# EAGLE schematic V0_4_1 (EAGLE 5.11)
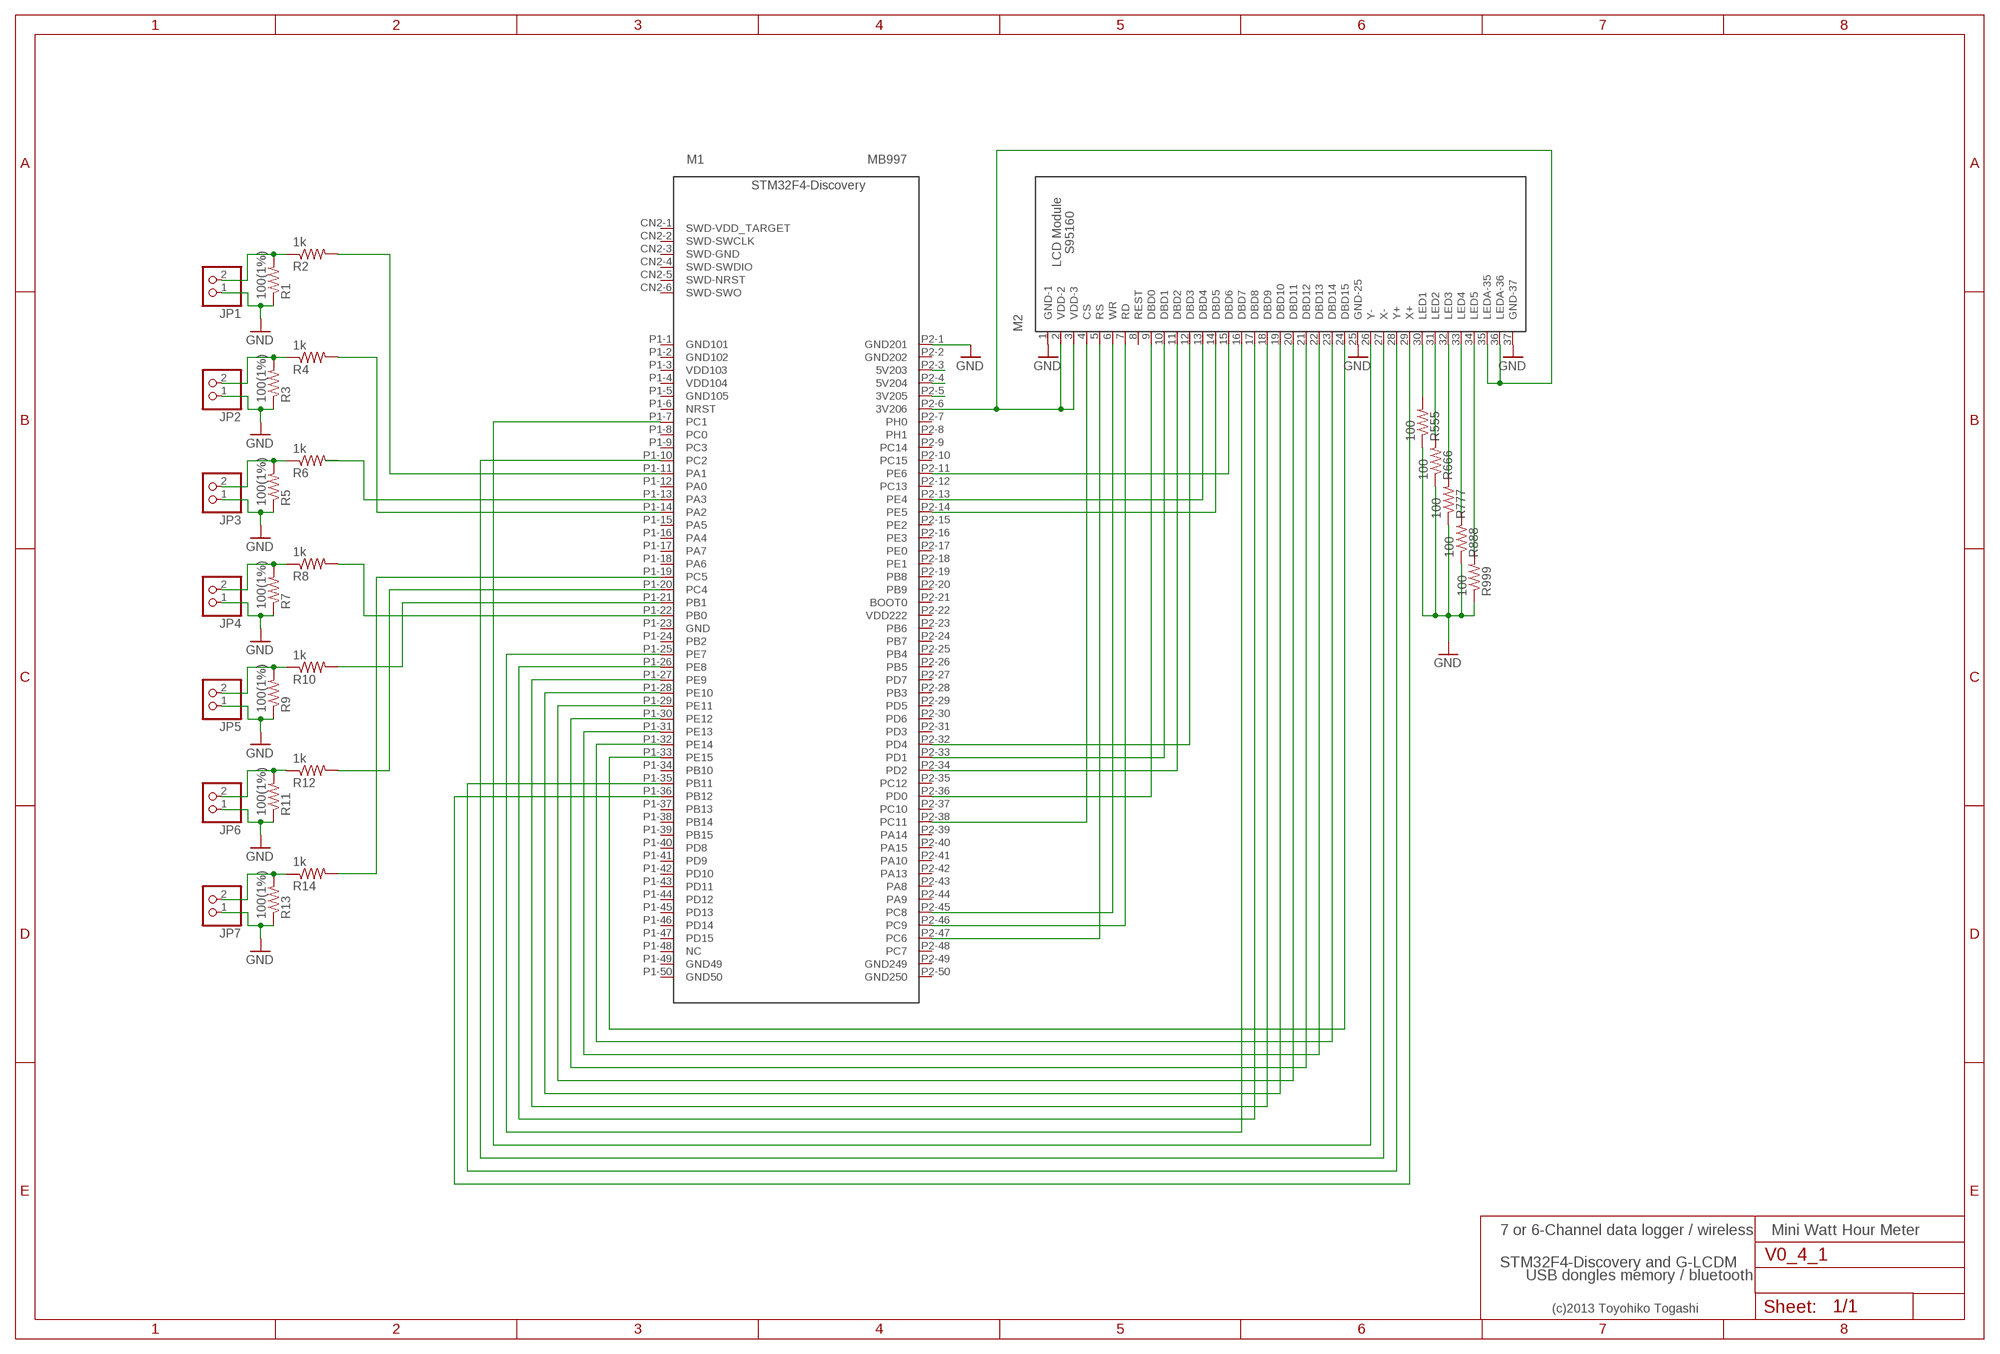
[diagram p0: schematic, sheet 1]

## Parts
JP1  PINHD-1X2  [1X02]
JP2  PINHD-1X2  [1X02]
JP3  PINHD-1X2  [1X02]
JP4  PINHD-1X2  [1X02]
JP5  PINHD-1X2  [1X02]
JP6  PINHD-1X2  [1X02]
JP7  PINHD-1X2  [1X02]
M1  MB997  [MB997]
M2  S95160  [S95160]
R1  100(1%)  R-US_0204/5  [0204/5]
R2  1k  R-US_0204/5  [0204/5]
R3  100(1%)  R-US_0204/5  [0204/5]
R4  1k  R-US_0204/5  [0204/5]
R5  100(1%)  R-US_0204/5  [0204/5]
R6  1k  R-US_0204/5  [0204/5]
R7  100(1%)  R-US_0204/5  [0204/5]
R8  1k  R-US_0204/5  [0204/5]
R9  100(1%)  R-US_0204/5  [0204/5]
R10  1k  R-US_0204/5  [0204/5]
R11  100(1%)  R-US_0204/5  [0204/5]
R12  1k  R-US_0204/5  [0204/5]
R13  100(1%)  R-US_0204/5  [0204/5]
R14  1k  R-US_0204/5  [0204/5]
R555  100  R-US_0204/5  [0204/5]
R666  100  R-US_0204/5  [0204/5]
R777  100  R-US_0204/5  [0204/5]
R888  100  R-US_0204/5  [0204/5]
R999  100  R-US_0204/5  [0204/5]

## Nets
GND: JP1.1 JP2.1 JP3.1 JP4.1 JP5.1 JP6.1 JP7.1 M1.P2-1(GND201) M2.1(GND-1) M2.25(GND-25) M2.37(GND-37) R1.1 R3.1 R5.1 R7.1 R9.1 R11.1 R13.1 R555.1 R666.1 R777.1 R888.1 R999.1
N$1: M1.P2-36(PD0) M2.9(DBD0)
N$2: M1.P2-33(PD1) M2.10(DBD1)
N$3: JP1.2 R1.2 R2.1
N$4: M1.P2-4(5V204)
N$5: M1.P2-3(5V203)
N$6: M1.P2-5(3V205)
N$7: M1.P1-11(PA1) R2.2
N$8: JP2.2 R3.2 R4.1
N$9: M1.P1-14(PA2) R4.2
N$10: JP3.2 R5.2 R6.1
N$11: M1.P2-34(PD2) M2.11(DBD2)
N$12: JP4.2 R7.2 R8.1
N$13: M1.P1-21(PB1) R10.2
N$14: M1.P2-6(3V206) M2.2(VDD-2) M2.3(VDD-3) M2.35(LEDA-35) M2.36(LEDA-36)
N$15: M1.P2-32(PD4) M2.12(DBD3)
N$16: M1.P1-20(PC4) R12.2
N$17: M1.P2-13(PE4) M2.13(DBD4)
N$18: M1.P2-14(PE5) M2.14(DBD5)
N$19: M1.P2-11(PE6) M2.15(DBD6)
N$20: M1.P1-19(PC5) R14.2
N$21: M1.P1-25(PE7) M2.16(DBD7)
N$22: M1.P1-26(PE8) M2.17(DBD8)
N$23: M1.P1-27(PE9) M2.18(DBD9)
N$24: M1.P1-28(PE10) M2.19(DBD10)
N$25: M1.P1-13(PA3)
N$26: M1.P1-22(PB0) R8.2
N$27: M1.P1-29(PE11) M2.20(DBD11)
N$28: M1.P1-30(PE12) M2.21(DBD12)
N$29: M1.P1-31(PE13) M2.22(DBD13)
N$30: M1.P1-32(PE14) M2.23(DBD14)
N$31: M1.P2-47(PC6) M2.5(RS)
N$32: M1.P1-33(PE15) M2.24(DBD15)
N$33: M1.P2-45(PC8) M2.6(WR)
N$34: M1.P2-46(PC9) M2.7(RD)
N$35: M1.P2-38(PC11) M2.4(CS)
N$36: M1.P1-7(PC1) M2.26(Y-)
N$37: M1.P1-10(PC2) M2.27(X-)
N$38: M1.P1-35(PB11) M2.28(Y+)
N$39: M1.P1-36(PB12) M2.29(X+)
N$40: JP5.2 R9.2 R10.1
N$41: JP6.2 R11.2 R12.1
N$42: M2.30(LED1) R555.2
N$43: M2.31(LED2) R666.2
N$44: M2.32(LED3) R777.2
N$45: M2.33(LED4) R888.2
N$46: M2.34(LED5) R999.2
N$47: JP7.2 R13.2 R14.1
Unconnected: M1.CN2-1(SWD-VDD_TARGET) M1.CN2-2(SWD-SWCLK) M1.CN2-3(SWD-GND) M1.CN2-4(SWD-SWDIO) M1.CN2-5(SWD-NRST) M1.CN2-6(SWD-SWO) M1.P1-1(GND101) M1.P1-2(GND102) M1.P1-3(VDD103) M1.P1-4(VDD104) M1.P1-5(GND105) M1.P1-6(NRST) M1.P1-8(PC0) M1.P1-9(PC3) M1.P1-12(PA0) M1.P1-15(PA5) M1.P1-16(PA4) M1.P1-17(PA7) M1.P1-18(PA6) M1.P1-23(GND) M1.P1-24(PB2) M1.P1-34(PB10) M1.P1-37(PB13) M1.P1-38(PB14) M1.P1-39(PB15) M1.P1-40(PD8) M1.P1-41(PD9) M1.P1-42(PD10) M1.P1-43(PD11) M1.P1-44(PD12) M1.P1-45(PD13) M1.P1-46(PD14) M1.P1-47(PD15) M1.P1-48(NC) M1.P1-49(GND49) M1.P1-50(GND50) M1.P2-2(GND202) M1.P2-7(PH0) M1.P2-8(PH1) M1.P2-9(PC14) M1.P2-10(PC15) M1.P2-12(PC13) M1.P2-15(PE2) M1.P2-16(PE3) M1.P2-17(PE0) M1.P2-18(PE1) M1.P2-19(PB8) M1.P2-20(PB9) M1.P2-21(BOOT0) M1.P2-22(VDD222) M1.P2-23(PB6) M1.P2-24(PB7) M1.P2-25(PB4) M1.P2-26(PB5) M1.P2-27(PD7) M1.P2-28(PB3) M1.P2-29(PD5) M1.P2-30(PD6) M1.P2-31(PD3) M1.P2-35(PC12) M1.P2-37(PC10) M1.P2-39(PA14) M1.P2-40(PA15) M1.P2-41(PA10) M1.P2-42(PA13) M1.P2-43(PA8) M1.P2-44(PA9) M1.P2-48(PC7) M1.P2-49(GND249) M1.P2-50(GND250) M2.8(REST) R6.2

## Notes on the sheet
- 7 or 6-Channel data logger / wireless | Mini Watt Hour Meter
- STM32F4-Discovery and G-LCDM
- USB dongles memory / bluetooth
- (c)2013 Toyohiko Togashi

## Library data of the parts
JP1-JP7 = pinhead:PINHD-1X2: PIN HEADER
M1 = TOG:MB997: STMicroelectronics STM32F4-Discovery
M2 = TOG:S95160: 3.2' TFT LCD Module 240x320dot SUCCESS ELECTRONIC CO.,LTD.
R1-R14 R555 R666 R777 R888 R999 = rcl:R-US_: RESISTOR, American symbol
